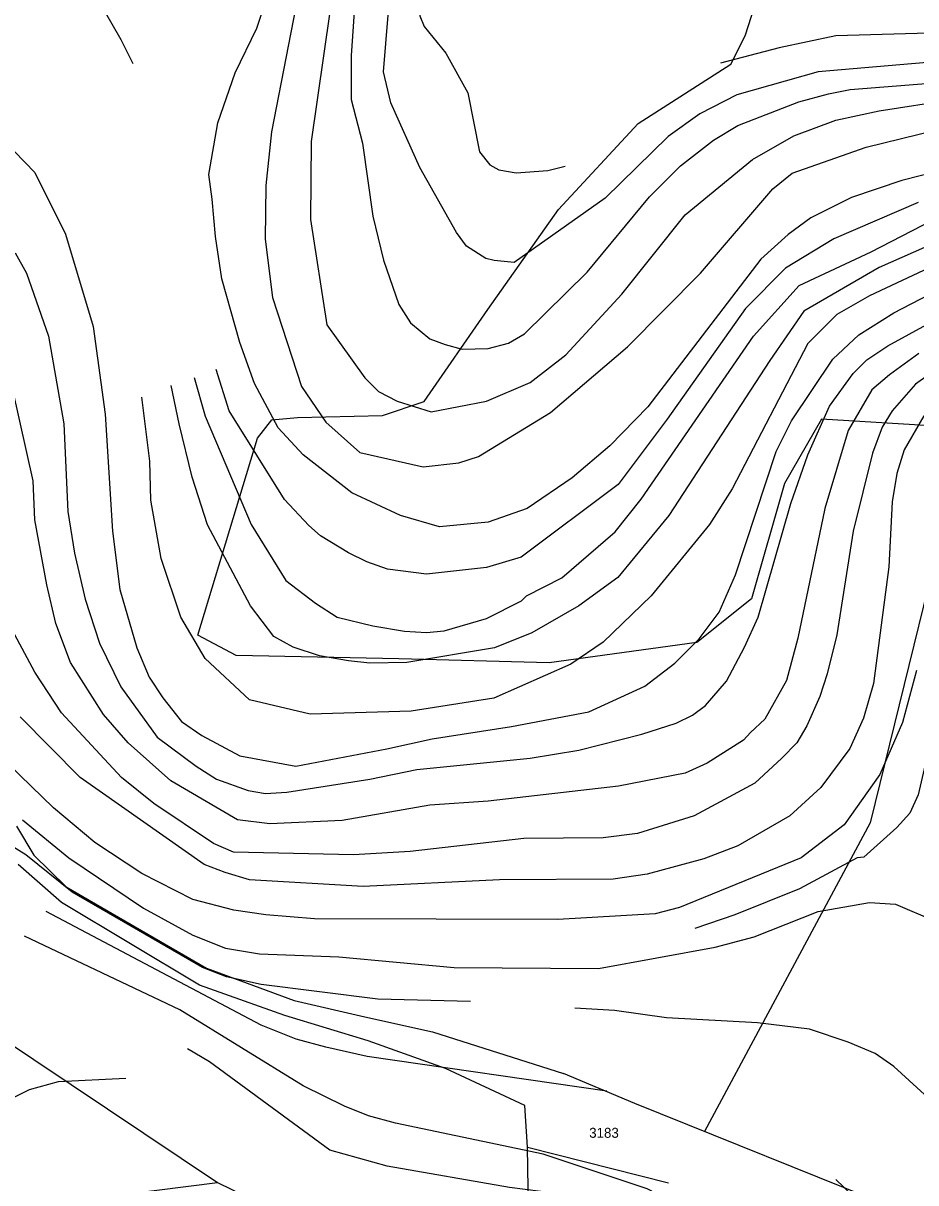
# Model space of a CAD drawing. Extents: x -555860 to -552701, y -1187050 to -1182291.
# Drawn here: x -554170.8 to -554018.2, y -1185774.2 to -1185576 of the extents above; entities that cross this region are included whole.
import ezdxf

# ---------------------------------------------------------------- set-up
doc = ezdxf.new("R2010")
doc.units = 0
for name, color, linetype in [('LEG_2b', 7, 'Continuous'), ('Level 40', 7, 'Continuous'), ('Level 41', 7, 'Continuous'), ('Level 42', 7, 'Continuous'), ('navrh_BV', 7, 'Continuous'), ('Poz předměty', 7, 'Continuous')]:
    doc.layers.add(name, color=color, linetype=linetype)

msp = doc.modelspace()

# ---------------------------------------------------------------- linework, layer by layer
at = {"layer": 'Level 40'}
for points in [[(-554014.95, -1185502.19), (-554019.6, -1185508.88), (-554025.92, -1185515.76), (-554030.84, -1185520.55), (-554040.55, -1185527.07), (-554051.09, -1185532.2), (-554077.43, -1185543.29), (-554089.64, -1185549.94), (-554099.76, -1185565.47), (-554102.81, -1185571.02), (-554102.95, -1185574.76), (-554102.25, -1185576.57), (-554098.51, -1185581.14), (-554094.77, -1185587.94), (-554092.76, -1185598.02), (-554091.02, -1185600.24), (-554089.49, -1185601.07), (-554086.48, -1185601.57), (-554081.12, -1185601.19), (-554078.15, -1185600.45)], [(-554003.11, -1185598.47), (-554020.58, -1185602.91), (-554029.18, -1185605.82), (-554036.11, -1185609.29), (-554040.03, -1185612.12), (-554044.71, -1185616.36), (-554063.98, -1185641.6), (-554070.5, -1185648.25), (-554076.91, -1185653.71), (-554084.64, -1185658.93), (-554091.3, -1185661.28), (-554099.62, -1185662.12), (-554106.28, -1185660.18), (-554114.59, -1185656.29), (-554122.91, -1185649.78), (-554127.21, -1185645.2), (-554131.23, -1185637.57), (-554133.74, -1185630.6), (-554136.8, -1185619.73), (-554137.92, -1185612.48), (-554138.48, -1185606.07), (-554139.07, -1185601.87), (-554137.51, -1185593.06), (-554134.56, -1185584.47), (-554130.82, -1185576.84), (-554128.85, -1185570.79)], [(-553797.62, -1185648.67), (-553808.16, -1185651.44), (-553813.43, -1185651.72), (-553820.22, -1185651.03), (-553858.49, -1185630.92), (-553864.46, -1185626.34), (-553886.23, -1185604.71), (-553894.44, -1185597.75), (-553911.32, -1185588.21), (-553921.17, -1185583.78), (-553931.57, -1185580.45), (-553953.47, -1185577.95), (-553988.21, -1185576.9), (-554031.88, -1185578.2), (-554041.54, -1185580.24), (-554051.58, -1185582.84)], [(-554175.88, -1185594.31), (-554168.81, -1185601.52), (-554163.54, -1185612.06), (-554158.83, -1185627.87), (-554156.75, -1185642.84), (-554155.5, -1185662.81), (-554154.25, -1185672.79), (-554151.34, -1185682.78), (-554149.26, -1185687.77), (-554146.92, -1185691.33), (-554143.71, -1185695.39), (-554140.23, -1185697.76), (-554133.73, -1185701.22), (-554124.16, -1185703.02), (-554108.64, -1185700.03), (-554100.84, -1185698.35), (-554087.28, -1185696.22), (-554074.11, -1185693.73), (-554064.54, -1185689.35), (-554059.41, -1185685.41), (-554055.25, -1185681.25), (-554051.78, -1185676.68), (-554049.01, -1185670.3), (-554042.08, -1185649.22), (-554039.44, -1185643.95), (-554032.37, -1185633.42), (-554027.93, -1185629.26), (-554021.96, -1185625.49), (-554012.82, -1185620.8)], [(-554018.09, -1185686.66), (-554020.45, -1185695.53), (-554024.33, -1185704.41), (-554030.43, -1185713), (-554037.78, -1185718.69), (-554058.58, -1185727.15), (-554062.74, -1185728.26), (-554079.38, -1185729.23), (-554120.97, -1185729.09), (-554129.29, -1185728.39), (-554134.76, -1185727.6), (-554141.77, -1185725.76), (-554150.51, -1185721.32), (-554158.55, -1185716.05), (-554165.62, -1185710.09), (-554177.12, -1185699)], [(-554082.27, -1185775.71), (-554087.65, -1185775.01), (-554108.56, -1185771.38), (-554118.34, -1185768.61), (-554138.95, -1185753.53), (-554142.67, -1185751.28)]]:
    msp.add_lwpolyline(points, dxfattribs=at)
at = {"layer": 'Level 41'}
for points in [[(-554113.35, -1185561.59), (-554114.73, -1185581.56), (-554114.73, -1185589.05), (-554112.79, -1185596.53), (-554110.99, -1185609.01), (-554109.19, -1185616.5), (-554106.55, -1185624.12), (-554104.59, -1185627.22), (-554101.28, -1185629.95), (-554098.65, -1185630.93), (-554095.74, -1185631.75), (-554091.3, -1185631.61), (-554087.81, -1185630.69), (-554085.06, -1185629.12), (-554074.38, -1185618.58), (-554063.71, -1185605.68), (-554058.44, -1185600.42), (-554052.75, -1185595.98), (-554048.59, -1185593.48), (-554038.19, -1185589.46), (-554033.1, -1185588.11), (-554029.43, -1185587.33), (-553994.12, -1185584.53)], [(-554123.4, -1185569.06), (-554128.32, -1185594.59), (-554129.29, -1185603.74), (-554129.43, -1185612.9), (-554128.18, -1185622.88), (-554123.19, -1185638.13), (-554119.03, -1185644.23), (-554113.21, -1185649.36), (-554102.39, -1185651.86), (-554096.29, -1185651.16), (-554092.96, -1185650.05), (-554080.62, -1185642.57), (-554067.45, -1185631.34), (-554054.97, -1185618.72), (-554042.63, -1185604.3), (-554039.3, -1185601.66), (-554026.69, -1185597.23), (-554005.33, -1185591.96)], [(-554002.28, -1185581.56), (-554034.87, -1185584.33), (-554048.79, -1185588.24), (-554055.13, -1185591.49), (-554060.52, -1185595.39), (-554071.28, -1185605.9), (-554086.86, -1185616.91), (-554090.28, -1185616.58), (-554091.72, -1185616.22), (-554094.98, -1185614.1), (-554096.71, -1185611.78), (-554102.95, -1185600.69), (-554107.94, -1185589.6), (-554109.19, -1185584.33), (-554107.94, -1185569.08)], [(-554158.22, -1185571.5), (-554154.1, -1185578.8), (-554152.05, -1185582.91)], [(-554118.34, -1185574.07), (-554121.53, -1185596.26), (-554121.67, -1185609.57), (-554118.89, -1185627.59), (-554112.38, -1185636.6), (-554110.02, -1185638.96), (-554106.83, -1185640.63), (-554101.01, -1185642.43), (-554091.58, -1185640.63), (-554084.09, -1185637.44), (-554077.99, -1185632.72), (-554068.42, -1185622.32), (-554057.61, -1185608.74), (-554046.1, -1185599.3), (-554039.03, -1185595.28), (-554031.86, -1185592.57), (-554024.47, -1185590.99), (-554011.99, -1185589.04)], [(-554017.81, -1185606.66), (-554032.23, -1185612.89), (-554040.48, -1185617.89), (-554047.31, -1185624.75), (-554060.69, -1185643.71), (-554069.05, -1185654.86), (-554085.67, -1185667.25), (-554091.58, -1185669.04), (-554101.84, -1185670.16), (-554108.49, -1185669.33), (-554112.02, -1185668.06), (-554115.15, -1185666.55), (-554119.94, -1185663.61), (-554121.94, -1185661.84), (-554126.1, -1185657.4), (-554135.57, -1185642.25), (-554137.8, -1185635.19)], [(-554141.54, -1185636.58), (-554139.65, -1185643.18), (-554131.79, -1185661.7), (-554125.88, -1185671.28), (-554120.83, -1185675.15), (-554117.09, -1185677.51), (-554110.99, -1185679.03), (-554105.58, -1185679.94), (-554101.84, -1185680.14), (-554098.79, -1185679.87), (-554091.58, -1185677.78), (-554085.58, -1185674.74), (-554084.76, -1185673.9), (-554078.71, -1185670.78), (-554069.61, -1185662.94), (-554065.15, -1185657.37), (-554045.91, -1185629.49), (-554038.11, -1185620.84), (-554025.85, -1185615.11), (-554015.32, -1185609.7)], [(-554008.94, -1185610.95), (-554024.47, -1185617.75), (-554037.36, -1185625.23), (-554043.12, -1185633.67), (-554060.41, -1185660.16), (-554069.12, -1185670.74), (-554075.77, -1185675.57), (-554083.84, -1185680.19), (-554090.19, -1185682.78), (-554105.17, -1185685.27), (-554111.52, -1185685.39), (-554115.15, -1185685), (-554120.14, -1185684.16), (-554124.64, -1185682.66), (-554127.91, -1185680.84), (-554131.93, -1185675.57), (-554139.28, -1185661.77), (-554141.88, -1185653.59), (-554144.11, -1185644.48), (-554145.5, -1185637.95)], [(-554172.14, -1185615.25), (-554170.2, -1185618.72), (-554166.45, -1185629.53), (-554163.82, -1185644.51), (-554163.12, -1185659.48), (-554162.02, -1185666.57), (-554160.21, -1185674.46), (-554157.72, -1185681.95), (-554154.11, -1185689.43), (-554147.87, -1185698.03), (-554141.22, -1185703.02), (-554137.76, -1185705.19), (-554132.34, -1185707.18), (-554129.34, -1185707.66), (-554125.69, -1185707.46), (-554111.52, -1185705.19), (-554103.5, -1185703.58), (-554084.09, -1185701.63), (-554075.77, -1185700.25), (-554065.03, -1185697.51), (-554059.13, -1185695.67), (-554056.37, -1185694.3), (-554054.14, -1185692.62), (-554050.53, -1185688.46), (-554047.46, -1185682.66), (-554045.13, -1185677.51), (-554039.58, -1185658.1), (-554036.67, -1185649.78), (-554032.93, -1185641.46), (-554028.9, -1185635.91), (-554026.55, -1185633.55), (-554022.95, -1185631.18), (-554011.43, -1185624.82)], [(-554013.1, -1185616.5), (-554026.13, -1185622.6), (-554031.68, -1185625.79), (-554036.67, -1185630.78), (-554049.56, -1185655.6), (-554053.45, -1185661.7), (-554063.43, -1185673.9), (-554071.61, -1185681.81), (-554077.16, -1185685.55), (-554090.33, -1185691.37), (-554104.46, -1185693.61), (-554121.7, -1185694.12), (-554132.07, -1185691.65), (-554139.69, -1185684.58), (-554143.85, -1185677.51), (-554147.18, -1185667.52), (-554148.98, -1185657.54), (-554149.12, -1185650.89), (-554150.49, -1185639.92)], [(-554012.54, -1185633.69), (-554018.23, -1185637.71), (-554022.25, -1185642.29), (-554023.94, -1185645.04), (-554025.58, -1185649.5), (-554028.9, -1185662.81), (-554031.68, -1185680.56), (-554033.34, -1185687.21), (-554034.58, -1185691.08), (-554036.81, -1185696.09), (-554038.55, -1185699), (-554041.11, -1185701.63), (-554045.68, -1185705.93), (-554056.08, -1185711.48), (-554065.79, -1185714.53), (-554071.61, -1185715.22), (-554085.2, -1185715.36), (-554104.61, -1185717.58), (-554114.32, -1185718.14), (-554134.84, -1185717.72), (-554138.23, -1185716.21), (-554148.43, -1185709.4), (-554153.97, -1185704.96), (-554164.23, -1185693.87), (-554168.81, -1185686.94), (-554172.66, -1185679.69)], [(-554017.67, -1185632.44), (-554022.7, -1185636.13), (-554025.71, -1185638.68), (-554029.74, -1185645.62), (-554033.76, -1185658.93), (-554038.33, -1185681.11), (-554040.28, -1185688.36), (-554044.02, -1185694.98), (-554046.47, -1185697.27), (-554047.62, -1185698.58), (-554053.86, -1185702.47), (-554057.61, -1185704.2), (-554068.99, -1185706.43), (-554091.3, -1185708.98), (-554101.28, -1185709.68), (-554116.26, -1185712.31), (-554128.6, -1185712.86), (-554134.15, -1185712.17), (-554145.52, -1185705.52), (-554152.86, -1185699), (-554157.02, -1185694.15), (-554162.71, -1185685.27), (-554165.2, -1185678.62), (-554166.72, -1185672.02), (-554168.81, -1185660.87), (-554169.09, -1185654.21), (-554172.55, -1185638.68)], [(-554016.84, -1185643.12), (-554020.17, -1185648.95), (-554021.46, -1185652.96), (-554022.25, -1185657.82), (-554022.8, -1185668.91), (-554025.44, -1185688.88), (-554027.16, -1185694.79), (-554029.46, -1185699.97), (-554034.45, -1185706.63), (-554039.72, -1185711.48), (-554048.59, -1185716.61), (-554054.42, -1185718.83), (-554064.12, -1185721.46), (-554069.95, -1185722.29), (-554089.36, -1185722.43), (-554112.65, -1185723.54), (-554132.07, -1185722.43), (-554136.25, -1185721.16), (-554139.83, -1185719.8), (-554161.04, -1185704.96), (-554171.31, -1185694.56)], [(-554094.33, -1185743.24), (-554110.16, -1185742.82), (-554130.12, -1185740.32), (-554136, -1185738.98), (-554140.11, -1185737.41), (-554162.43, -1185724.51), (-554170.33, -1185718.13), (-554177.82, -1185713.56), (-554185.59, -1185711.2), (-554189.67, -1185711.01)], [(-554170.89, -1185712.17), (-554162.98, -1185718.69), (-554150.23, -1185727.28), (-554141.77, -1185731.86), (-554136.22, -1185734.08), (-554130.4, -1185735.05), (-554116.81, -1185735.61), (-554097.12, -1185737.41), (-554072.44, -1185737.55), (-554052.48, -1185733.94), (-554045.82, -1185732.14), (-554034.87, -1185727.84), (-554026.13, -1185726.32), (-554021.69, -1185726.59), (-554014.97, -1185729.41)], [(-554071.01, -1185758.57), (-554111.99, -1185752.6), (-554119.03, -1185751), (-554124.12, -1185749.63), (-554130.12, -1185747.25), (-554166.83, -1185727.81)], [(-554040.41, -1185788.3), (-554052.75, -1185781.08), (-554064.12, -1185775.26), (-554081.87, -1185769.3), (-554107.11, -1185764.03), (-554111.74, -1185762.74), (-554115.84, -1185761.12), (-554122.91, -1185757.65), (-554143.99, -1185744.62), (-554170.56, -1185732.05)], [(-554029.74, -1185750.17), (-554036.39, -1185747.95), (-554045.27, -1185746.84), (-554060.8, -1185746), (-554069.67, -1185744.76), (-554076.47, -1185744.38)], [(-553990.22, -1185794.53), (-554006.3, -1185771.52), (-554014.07, -1185761.53), (-554021.97, -1185754.32), (-554025.15, -1185752.1), (-554029.74, -1185750.17)], [(-554153.21, -1185756.36), (-554164.79, -1185756.96), (-554169.78, -1185758.34), (-554178.1, -1185762.5), (-554188.36, -1185770.41), (-554203.2, -1185787.46), (-554207.91, -1185795.23), (-554217.89, -1185815.05), (-554221.78, -1185828.65), (-554223.86, -1185840.15)], [(-554019.2, -1185785.8), (-554031.89, -1185773.62)]]:
    msp.add_lwpolyline(points, dxfattribs=at)
at = {"layer": 'Level 42'}
msp.add_lwpolyline([(-554012.82, -1185672.04), (-554013.42, -1185682.24), (-554015.45, -1185697.75), (-554017.81, -1185707.87), (-554019.21, -1185711.01), (-554021.44, -1185713.49), (-554027.1, -1185718.55), (-554028.21, -1185718.69), (-554038.06, -1185723.96), (-554049.15, -1185728.4), (-554055.94, -1185730.75)], dxfattribs=at)
at = {"layer": 'navrh_BV'}
for p, q in [((-554047.36, -1185578.19), (-554034.66, -1185537.98)), ((-554049.8, -1185583.01), (-554047.36, -1185578.19)), ((-554065.68, -1185593.14), (-554049.8, -1185583.01)), ((-554079.28, -1185607.86), (-554065.68, -1185593.14)), ((-554091.34, -1185624.94), (-554079.28, -1185607.86)), ((-554102.25, -1185640.66), (-554091.34, -1185624.94)), ((-554109.36, -1185643.08), (-554102.25, -1185640.66)), ((-554130.72, -1185646.95), (-554128.26, -1185643.83)), ((-554128.26, -1185643.83), (-554123.87, -1185643.43)), ((-554123.87, -1185643.43), (-554109.36, -1185643.08)), ((-554034.33, -1185643.68), (-554040.63, -1185654.7)), ((-554009.42, -1185645.24), (-554034.33, -1185643.68)), ((-554140.95, -1185680.6), (-554130.72, -1185646.95)), ((-554040.63, -1185654.7), (-554046.27, -1185674.38)), ((-554046.27, -1185674.38), (-554055.65, -1185681.86)), ((-554134.37, -1185684.08), (-554140.95, -1185680.6)), ((-554055.65, -1185681.86), (-554080.89, -1185685.36)), ((-554106.56, -1185684.66), (-554134.37, -1185684.08)), ((-554080.89, -1185685.36), (-554106.56, -1185684.66)), ((-554171.94, -1185713.23), (-554168.98, -1185718.23)), ((-554168.98, -1185718.23), (-554163.41, -1185723.6)), ((-554164.23, -1185726.28), (-554171.66, -1185719.81)), ((-554163.41, -1185723.6), (-554139.42, -1185737.51)), ((-554140.61, -1185740.42), (-554164.23, -1185726.28)), ((-554139.42, -1185737.51), (-554124.46, -1185743.03)), ((-554126.03, -1185745.61), (-554140.61, -1185740.42)), ((-554124.46, -1185743.03), (-554112.37, -1185745.86)), ((-554111.78, -1185749.93), (-554126.03, -1185745.61)), ((-554112.37, -1185745.86), (-554100.81, -1185748.42)), ((-554177.07, -1185747.73), (-554137.54, -1185774.16)), ((-554100.81, -1185748.42), (-554078.43, -1185755.55)), ((-554098.61, -1185754.68), (-554111.78, -1185749.93)), ((-554085.01, -1185761.01), (-554098.61, -1185754.68)), ((-554066.24, -1185760.67), (-554078.43, -1185755.55)), ((-554018.64, -1185779.78), (-554066.24, -1185760.67)), ((-554084.59, -1185768.1), (-554085.01, -1185761.01)), ((-554084.59, -1185768.1), (-554060.49, -1185774.23)), ((-554084.28, -1185785.25), (-554084.59, -1185768.1)), ((-554153.32, -1185776.15), (-554137.54, -1185774.16)), ((-554137.54, -1185774.16), (-554130.2, -1185777.76))]:
    msp.add_line(p, q, dxfattribs=at)
at = {"layer": 'Poz předměty'}
msp.add_lwpolyline([(-554009.42, -1185645.24), (-554025.99, -1185712.69), (-554054.32, -1185765.46)], dxfattribs=at)

# ---------------------------------------------------------------- texts
at = {"layer": 'LEG_2b'}
msp.add_text('3183', height=1.7, dxfattribs=at).set_placement((-554074.02, -1185766.51))

doc.saveas('drawing.dxf')
